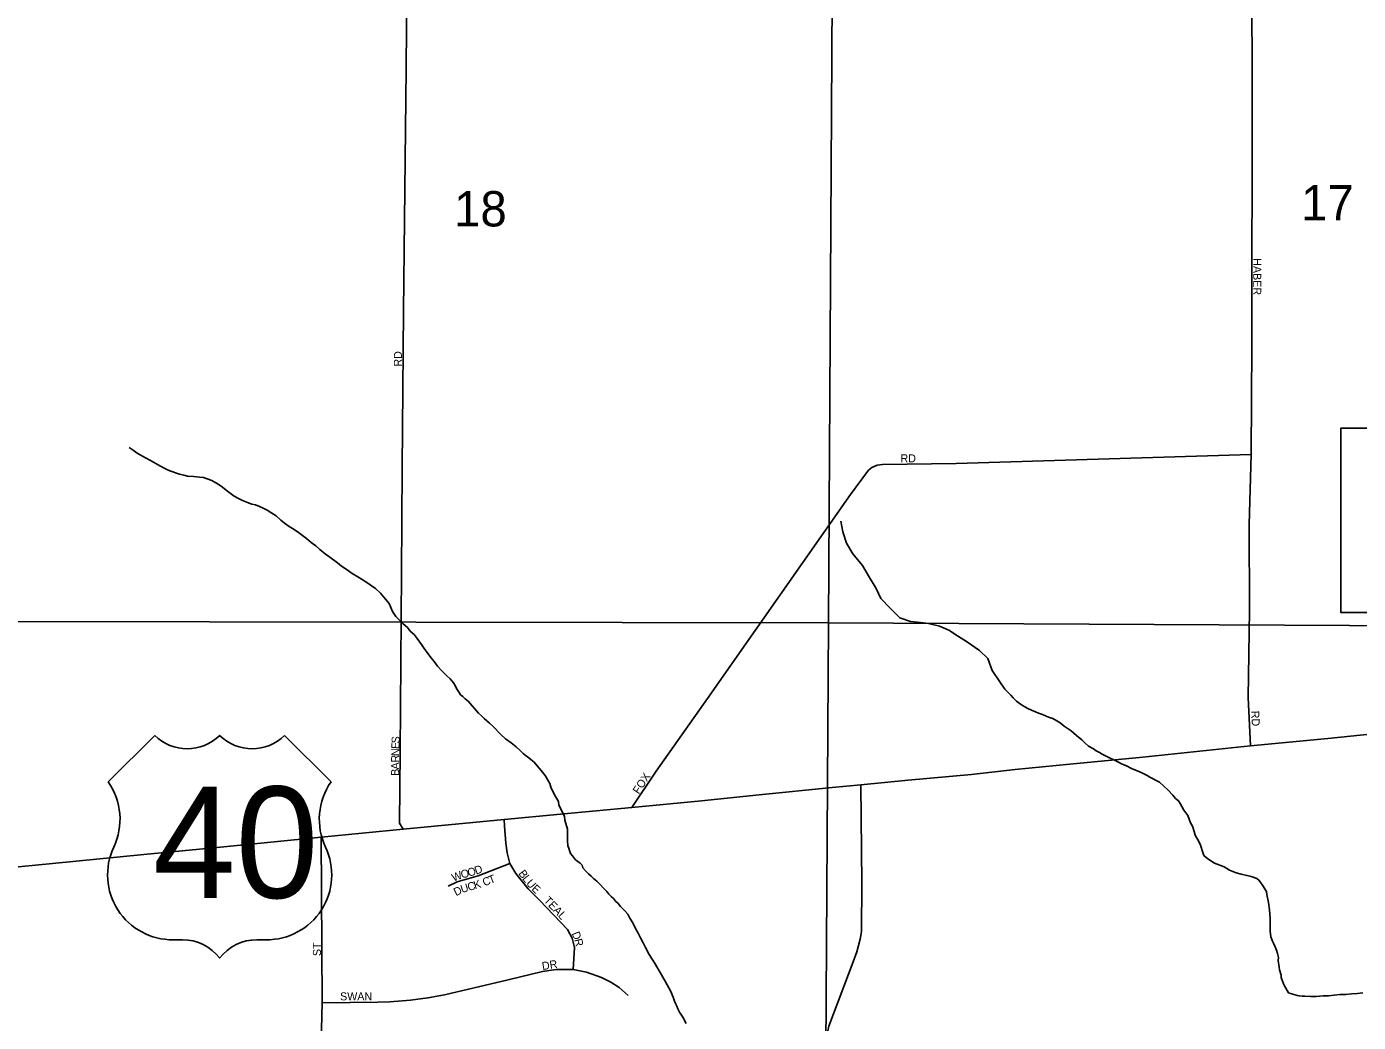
# Model space of a CAD drawing. Extents: x -209 to 4852, y 0 to 905.
# Drawn here: x 287.19 to 318.72, y 289.5 to 313.06 of the extents above; entities that cross this region are included whole.
import ezdxf

# ---------------------------------------------------------------- set-up
doc = ezdxf.new("R2010")
doc.units = 0
for name, color, linetype in [('GM_X_Airport_Location_Class_2', 7, 'Continuous'), ('GM_X_Airport_Location_Class_3', 7, 'Continuous'), ('GM_X_City_Street_Text', 7, 'Continuous'), ('GM_X_Corporation', 7, 'Continuous'), ('GM_X_County_Road', 7, 'Continuous'), ('GM_X_Interchange_Ramps', 7, 'Continuous'), ('GM_X_Minor_River', 7, 'Continuous'), ('GM_X_Township_Road_Text', 7, 'Continuous'), ('GM_X_US_Location', 7, 'Continuous')]:
    doc.layers.add(name, color=color, linetype=linetype)

msp = doc.modelspace()

# ---------------------------------------------------------------- linework, layer by layer
at = {"layer": 'GM_X_Airport_Location_Class_2'}
for points in [[(316.159, 296.04), (316.106, 297.187), (316.135, 299.241), (316.129, 301.278), (316.181, 302.937), (316.192, 305.534), (316.198, 311.508), (316.179, 319.381)], [(296.106, 294.065), (296.016, 294.208), (296.036, 295.898), (296.068, 300.128), (296.084, 302.62), (296.116, 306.329), (296.173, 312.059), (296.234, 318.965)], [(301.52, 294.585), (302.094, 295.443), (303.31, 297.164), (306.69, 301.991), (307.117, 302.562), (307.197, 302.629), (307.321, 302.683), (307.451, 302.699), (309.198, 302.723), (316.181, 302.937)], [(306.151, 276.018), (306.154, 278.445), (306.104, 278.631), (306.08, 280.477), (306.078, 284.16), (306.1, 288.69), (306.105, 288.965), (306.136, 289.184), (306.182, 289.408), (306.755, 290.932), (306.847, 291.166), (306.919, 291.465), (306.951, 291.65), (306.96, 292.793), (306.941, 295.117)], [(300.13, 290.744), (300.161, 291.268), (300.106, 291.489), (299.994, 291.696), (299.336, 292.383), (299.066, 292.656), (298.77, 293.019), (298.63, 293.257), (298.57, 293.505), (298.532, 293.74), (298.5, 294.138), (298.493, 294.299)], [(294.158, 288.703), (294.19, 289.961), (294.162, 293.878)], [(297.169, 292.72), (297.379, 292.826), (297.883, 292.966), (298.63, 293.257)], [(294.19, 289.961), (295.507, 289.974), (295.79, 289.981), (296.279, 290.019), (296.689, 290.076), (297.084, 290.146), (298.591, 290.505), (299.405, 290.702), (299.729, 290.75), (300.13, 290.744), (300.441, 290.683), (300.797, 290.559), (301.023, 290.45), (301.22, 290.321), (301.427, 290.13)]]:
    msp.add_lwpolyline(points, dxfattribs=at)
at = {"layer": 'GM_X_Corporation'}
msp.add_lwpolyline([(286.672, 293.142), (287.804, 293.256), (289.962, 293.469), (291.777, 293.64), (294.162, 293.878), (296.106, 294.065), (298.493, 294.299), (299.832, 294.423), (301.52, 294.585), (303.163, 294.743), (304.531, 294.879), (306.257, 295.051), (306.941, 295.117), (308.057, 295.229), (309.554, 295.364), (310.593, 295.477), (311.888, 295.606), (313.614, 295.774), (316.159, 296.04), (317.99, 296.214), (320.136, 296.435)], dxfattribs=at)
at = {"layer": 'GM_X_County_Road'}
for points in [[(289.615, 303.1), (289.712, 303.037), (289.809, 302.966), (290.004, 302.855), (290.123, 302.791), (290.251, 302.726), (290.348, 302.671), (290.491, 302.591), (290.581, 302.55), (290.807, 302.468), (290.912, 302.443), (291.003, 302.425), (291.14, 302.414), (291.284, 302.402), (291.375, 302.392), (291.578, 302.319), (291.728, 302.231), (291.825, 302.16), (291.914, 302.089), (292.108, 301.947), (292.205, 301.892), (292.303, 301.843), (292.416, 301.802), (292.521, 301.762), (292.612, 301.744), (292.702, 301.704), (292.792, 301.663), (292.882, 301.615), (292.994, 301.544), (293.099, 301.488), (293.21, 301.378), (293.299, 301.308), (293.404, 301.229), (293.523, 301.157), (293.628, 301.086), (293.725, 301.015), (293.814, 300.944), (293.925, 300.85), (294.037, 300.771), (294.134, 300.685), (294.268, 300.575), (294.372, 300.504), (294.551, 300.37), (294.648, 300.292), (294.752, 300.22), (294.894, 300.118), (295.029, 300.038), (295.133, 299.975), (295.223, 299.919), (295.327, 299.848), (295.447, 299.761), (295.565, 299.652), (295.683, 299.512), (295.772, 299.411), (295.814, 299.311), (295.85, 299.219), (295.93, 299.103), (296.108, 298.931), (296.205, 298.845), (296.271, 298.752), (296.367, 298.673), (296.433, 298.58), (296.536, 298.441), (296.602, 298.348), (296.675, 298.247), (296.763, 298.131), (296.836, 298.038), (296.917, 297.929), (297.02, 297.812), (297.131, 297.703), (297.22, 297.625)], [(310.35, 297.379), (310.225, 297.555), (310.047, 297.824), (309.946, 298.108), (309.745, 298.294), (309.467, 298.498), (309.226, 298.647), (309.023, 298.78), (308.804, 298.876), (308.538, 298.934), (308.348, 298.96), (308.113, 298.98), (307.863, 299.069), (307.631, 299.302), (307.415, 299.526), (307.298, 299.765), (307.121, 300.065), (306.974, 300.311), (306.751, 300.582), (306.596, 300.836), (306.51, 301.104), (306.461, 301.356)], [(299.574, 295.153), (299.463, 295.337), (299.375, 295.46), (299.278, 295.569), (299.204, 295.654), (299.129, 295.716), (299.076, 295.755), (298.994, 295.817), (298.942, 295.863), (298.875, 295.933), (298.778, 296.018), (298.658, 296.112), (298.53, 296.205), (298.418, 296.306), (298.225, 296.507), (298.15, 296.577), (298.083, 296.631), (298.023, 296.685), (297.956, 296.747), (297.889, 296.817), (297.643, 297.095), (297.569, 297.157), (297.516, 297.211), (297.464, 297.25), (297.427, 297.304), (297.368, 297.396), (297.339, 297.465), (297.295, 297.535), (297.22, 297.625)], [(316.802, 291.129), (316.78, 291.206), (316.737, 291.298), (316.707, 291.367), (316.686, 291.42), (316.642, 291.52), (316.629, 291.657), (316.624, 291.802), (316.627, 291.954), (316.608, 292.159), (316.589, 292.334), (316.546, 292.525), (316.54, 292.594), (316.444, 292.74), (316.37, 292.855), (316.311, 292.902), (316.205, 292.942), (316.145, 292.958), (316.076, 292.974), (315.94, 293), (315.819, 293.032), (315.669, 293.096), (315.541, 293.174), (315.307, 293.262), (315.15, 293.363), (315.06, 293.449), (315.031, 293.518), (314.981, 293.693), (314.937, 293.778), (314.849, 293.924), (314.828, 294.015), (314.792, 294.137), (314.74, 294.222), (314.675, 294.39), (314.631, 294.452), (314.587, 294.521), (314.498, 294.675), (314.454, 294.736), (314.387, 294.798), (314.32, 294.876), (314.216, 294.992), (314.006, 295.178), (313.781, 295.296), (313.713, 295.335), (313.578, 295.406), (313.518, 295.43), (313.344, 295.501), (313.224, 295.564), (313.126, 295.604), (313.021, 295.659), (312.931, 295.706), (312.825, 295.754), (312.742, 295.793), (312.652, 295.84), (312.585, 295.88), (312.509, 295.926), (312.442, 295.966), (312.329, 296.036), (312.24, 296.114), (312.173, 296.183), (312.045, 296.284), (311.918, 296.393), (311.753, 296.51), (311.656, 296.588), (311.581, 296.635), (311.483, 296.69), (311.408, 296.714), (311.325, 296.746), (311.235, 296.785), (311.144, 296.817), (311.069, 296.849), (310.978, 296.881), (310.888, 296.928), (310.82, 296.96), (310.715, 297.023), (310.626, 297.1), (310.543, 297.178), (310.491, 297.239), (310.424, 297.301), (310.35, 297.379)], [(302.802, 289.47), (302.721, 289.616), (302.648, 289.739), (302.604, 289.816), (302.582, 289.877), (302.56, 289.931), (302.531, 290), (302.495, 290.091), (302.429, 290.245), (302.312, 290.452), (302.187, 290.675), (302.054, 290.905), (301.929, 291.105), (301.841, 291.266), (301.782, 291.381), (301.731, 291.481), (301.665, 291.611), (301.599, 291.734), (301.54, 291.849), (301.474, 291.964), (301.423, 292.057), (301.363, 292.126), (301.251, 292.242), (301.192, 292.311), (301.132, 292.366), (301.08, 292.427), (301.028, 292.474), (300.976, 292.528), (300.924, 292.59), (300.849, 292.675), (300.767, 292.76), (300.685, 292.837), (300.611, 292.899), (300.551, 292.954), (300.491, 293.008), (300.417, 293.085), (300.357, 293.155), (300.343, 293.216), (300.291, 293.262), (300.186, 293.34), (300.112, 293.44), (300.067, 293.494), (300.038, 293.563), (300.024, 293.617), (300.002, 293.678), (299.997, 293.8), (299.991, 293.906), (299.994, 294.066), (299.93, 294.28), (299.924, 294.379), (299.792, 294.64), (299.779, 294.723), (299.683, 294.885), (299.603, 295.061), (299.574, 295.153)], [(318.819, 290.196), (318.697, 290.183), (318.553, 290.171), (318.416, 290.158), (318.279, 290.153), (318.006, 290.127), (317.884, 290.122), (317.793, 290.116), (317.717, 290.11), (317.633, 290.111), (317.58, 290.105), (317.451, 290.114), (317.383, 290.116), (317.322, 290.124), (317.269, 290.133), (317.164, 290.165), (317.065, 290.197), (316.97, 290.359), (316.94, 290.412), (316.89, 290.558), (316.891, 290.611), (316.848, 290.741), (316.841, 290.802), (316.821, 290.962), (316.823, 291.03), (316.802, 291.129)]]:
    msp.add_lwpolyline(points, dxfattribs=at)
at = {"layer": 'GM_X_Interchange_Ramps'}
for p, q in [((290.223, 296.285), (289.124, 295.187)), ((294.397, 295.187), (293.299, 296.285)), ((290.662, 291.451), (290.882, 291.451)), ((292.64, 291.451), (292.859, 291.451))]:
    msp.add_line(p, q, dxfattribs=at)
for centre, radius, start, end in [((290.992, 297.07), 1.099, 225.573, 314.427), ((292.53, 297.07), 1.099, 225.573, 314.427), ((287.864, 294.305), 1.538, 334.5471, 35.0009), ((295.657, 294.305), 1.538, 144.9991, 205.4529), ((290.645, 292.989), 1.538, 154.8319, 270.6383), ((292.876, 292.989), 1.538, 269.3617, 25.1681), ((290.882, 290.353), 1.099, 36.8699, 90), ((292.64, 290.353), 1.099, 90, 143.1301)]:
    msp.add_arc(centre, radius, start, end, dxfattribs=at)
at = {"layer": 'GM_X_Minor_River'}
for points in [[(306.294, 319.133), (326.186, 319.462), (326.211, 298.849), (306.169, 298.948)], [(286.739, 319.003), (306.294, 319.133), (306.169, 298.948), (286.633, 298.983)], [(286.633, 298.983), (306.169, 298.948), (306.048, 278.677), (286.724, 278.709)], [(306.169, 298.948), (326.211, 298.849), (326.25, 278.99), (306.048, 278.677)]]:
    msp.add_lwpolyline(points, close=True, dxfattribs=at)
at = {"layer": 'GM_X_US_Location'}
for points in [[(319.804, 303.556), (318.297, 303.556), (318.297, 299.198), (320.543, 299.198)], [(320.543, 299.198), (318.297, 299.198), (318.297, 303.556), (319.804, 303.556)], [(320.543, 299.198), (318.297, 299.198), (318.297, 303.556), (319.804, 303.556)]]:
    msp.add_lwpolyline(points, dxfattribs=at)

# ---------------------------------------------------------------- texts
at = {"layer": 'GM_X_Airport_Location_Class_3'}
for s, height, rotation, p in [('HABER', 0.1894, 270, (316.227, 307.581)), ('RD', 0.1894, 90, (296.075, 305.015)), ('RD', 0.1894, 0, (307.877, 302.75)), ('RD', 0.1894, 273.011, (316.177, 296.866)), ('E', 0.189, 87.4992, (296.012, 295.962)), ('S', 0.189, 87.39, (296.017, 296.096)), ('R', 0.189, 89.9636, (296.009, 295.648)), ('N', 0.189, 88.9836, (296.009, 295.797)), ('A', 0.189, 89.9703, (296.008, 295.481)), ('B', 0.189, 89.9757, (296.008, 295.331)), ('FOX', 0.1894, 56.885, (301.681, 294.884)), ('D', 0.189, 19.7313, (297.832, 292.992)), ('W', 0.189, 21.0864, (297.298, 292.823)), ('O', 0.189, 15.2609, (297.495, 292.899)), ('O', 0.189, 15.3118, (297.656, 292.943)), ('K', 0.189, 16.8321, (297.804, 292.646)), ('C', 0.189, 20.4503, (298.023, 292.715)), ('T', 0.189, 21.712, (298.168, 292.769)), ('B', 0.189, 306.7728, (298.823, 293.018)), ('L', 0.189, 307.892, (298.915, 292.895)), ('U', 0.189, 310.5581, (299.003, 292.782)), ('D', 0.189, 27.3372, (297.357, 292.481)), ('U', 0.189, 17.6539, (297.497, 292.554)), ('C', 0.189, 15.4117, (297.654, 292.604)), ('E', 0.189, 317.5977, (299.129, 292.638)), ('TEAL', 0.1894, 313.2094, (299.42, 292.372)), ('D', 0.189, 291.6127, (300.091, 291.601)), ('ST', 0.1894, 90, (294.158, 291.065)), ('R', 0.189, 284.3956, (300.15, 291.452)), ('DR', 0.1894, 8.9682, (299.405, 290.733)), ('SWAN', 0.1894, 0, (294.611, 290.017))]:
    msp.add_text(s, height=height, rotation=rotation, dxfattribs=at).set_placement(p)
at = {"layer": 'GM_X_City_Street_Text'}
for s in ['/', '0']:
    msp.add_text(s, height=0.00379, dxfattribs=at).set_placement((291.759, 293.738))
msp.add_text('40', height=0.00379, rotation=0, dxfattribs=at).set_placement((290.977, 292.954))
at = {"layer": 'GM_X_Interchange_Ramps'}
msp.add_text('40', height=2.6367, dxfattribs=at).set_placement((290.177, 292.44))
at = {"layer": 'GM_X_Township_Road_Text'}
for s, p in [('17', (317.361, 308.476)), ('18', (297.311, 308.333))]:
    msp.add_text(s, height=0.8371, rotation=0, dxfattribs=at).set_placement(p)

doc.saveas('drawing.dxf')
